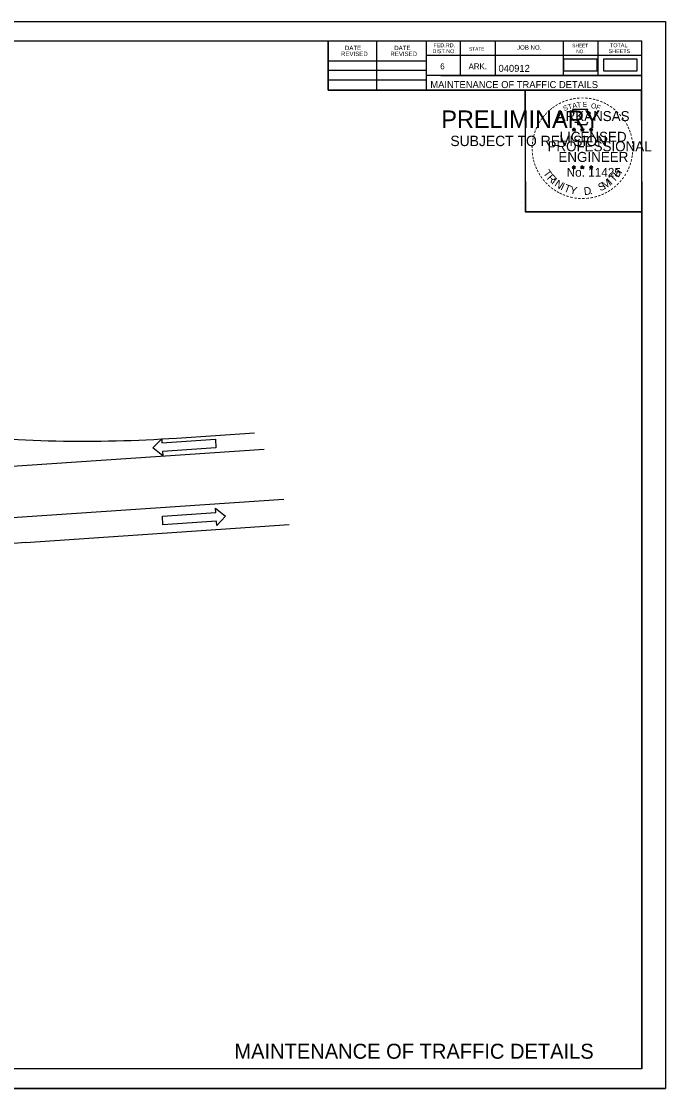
# Model space of a CAD drawing. Extents: x 13744624 to 13747958, y 3814079 to 3815145.
# Drawn here: x 13747314 to 13747958, y 3814079 to 3815145 of the extents above; entities that cross this region are included whole.
import ezdxf

# ---------------------------------------------------------------- set-up
doc = ezdxf.new("R2010")
doc.units = 0
for name, color, linetype in [('Default', 7, 'Continuous'), ('R_Border', 7, 'Continuous'), ('R_Border Notes', 7, 'Continuous'), ('R_Border PE', 7, 'Continuous'), ('R_Border Prem', 7, 'Continuous'), ('R_Exist Surface', 7, 'Continuous'), ('R_MOT', 7, 'Continuous'), ('R_No Plot', 7, 'Continuous')]:
    doc.layers.add(name, color=color, linetype=linetype)

msp = doc.modelspace()

# ---------------------------------------------------------------- linework, layer by layer
at = {"layer": 'Default'}
for points in [[(13747855.7, 3815096), (13747889.1, 3815096), (13747889.1, 3815107.6), (13747855.7, 3815107.6)], [(13747895.6, 3815096), (13747929, 3815096), (13747929, 3815107.6), (13747895.6, 3815107.6)]]:
    msp.add_lwpolyline(points, close=True, dxfattribs=at)
at = {"layer": 'R_Border'}
for p, q in [((13746352.9, 3815125.9), (13747933.8, 3815125.9)), ((13747620.6, 3815076.5), (13747620.6, 3815125.9)), ((13747669, 3815076.5), (13747669, 3815125.9)), ((13747718.3, 3815125.9), (13747718.3, 3815076.5)), ((13747752.5, 3815125.9), (13747752.5, 3815091.2)), ((13747787.2, 3815125.9), (13747787.2, 3815091.2)), ((13747855.1, 3815125.9), (13747855.1, 3815091.2)), ((13747889.8, 3815125.9), (13747889.8, 3815091.2)), ((13747933.8, 3814098.6), (13747933.8, 3815125.9)), ((13747620.6, 3815105.8), (13747718.3, 3815105.8)), ((13747933.8, 3815111.2), (13747718.3, 3815111.2)), ((13747933.8, 3815111.3), (13747933.8, 3815111.3)), ((13747620.6, 3815096.5), (13747718.3, 3815096.5)), ((13747620.6, 3815086.8), (13747718.3, 3815086.8)), ((13747933.8, 3815091.2), (13747718.3, 3815091.2)), ((13747733.1, 3815091.2), (13747933.8, 3815091.2)), ((13747933.8, 3815076.5), (13747620.6, 3815076.5)), ((13747933.8, 3814098.6), (13746352.9, 3814098.6))]:
    msp.add_line(p, q, dxfattribs=at)
at = {"layer": 'R_Border PE'}
for p, q in [((13747864.3, 3815037.8), (13747866, 3815037.2)), ((13747864.3, 3815037.8), (13747865.5, 3815037.6)), ((13747864.3, 3815037.8), (13747865.4, 3815037.2)), ((13747864.9, 3815035.8), (13747866, 3815037.2)), ((13747864.9, 3815035.8), (13747865.5, 3815037)), ((13747864.9, 3815035.8), (13747866, 3815036.8)), ((13747866, 3815039.1), (13747865.8, 3815037.8)), ((13747866, 3815037.2), (13747866, 3815039.1)), ((13747866, 3815039.1), (13747866.2, 3815037.8)), ((13747867.7, 3815037.8), (13747866, 3815037.2)), ((13747867.1, 3815035.8), (13747866, 3815037.2)), ((13747867.1, 3815035.8), (13747866, 3815036.8)), ((13747867.7, 3815037.8), (13747866.3, 3815037.6)), ((13747867.1, 3815035.8), (13747866.4, 3815037.2)), ((13747867.7, 3815037.8), (13747866.7, 3815037.3)), ((13747872.6, 3815037.8), (13747874.3, 3815037.2)), ((13747872.6, 3815037.8), (13747873.9, 3815037.6)), ((13747872.6, 3815037.8), (13747873.8, 3815037.2)), ((13747873.3, 3815035.8), (13747874.3, 3815037.2)), ((13747873.3, 3815035.8), (13747873.9, 3815037)), ((13747873.3, 3815035.8), (13747874.3, 3815036.8)), ((13747874.3, 3815039.1), (13747874.1, 3815037.8)), ((13747874.3, 3815037.2), (13747874.3, 3815039.1)), ((13747874.3, 3815039.1), (13747874.6, 3815037.8)), ((13747876.1, 3815037.8), (13747874.3, 3815037.2)), ((13747875.4, 3815035.8), (13747874.3, 3815037.2)), ((13747875.4, 3815035.8), (13747874.3, 3815036.8)), ((13747876.1, 3815037.8), (13747874.7, 3815037.6)), ((13747875.4, 3815035.8), (13747874.7, 3815037.2)), ((13747876.1, 3815037.8), (13747875.1, 3815037.3)), ((13747881.4, 3815037.7), (13747883.2, 3815037.2)), ((13747881.4, 3815037.7), (13747882.7, 3815037.5)), ((13747881.4, 3815037.7), (13747882.6, 3815037.1)), ((13747882.1, 3815035.7), (13747883.2, 3815037.2)), ((13747882.1, 3815035.7), (13747882.7, 3815036.9)), ((13747882.1, 3815035.7), (13747883.2, 3815036.8)), ((13747883.2, 3815039), (13747883, 3815037.7)), ((13747883.2, 3815037.2), (13747883.2, 3815039)), ((13747883.2, 3815039), (13747883.4, 3815037.8)), ((13747884.9, 3815037.7), (13747883.2, 3815037.2)), ((13747884.2, 3815035.7), (13747883.2, 3815037.2)), ((13747884.2, 3815035.7), (13747883.2, 3815036.8)), ((13747884.9, 3815037.7), (13747883.5, 3815037.5)), ((13747884.2, 3815035.7), (13747883.5, 3815037.2)), ((13747884.9, 3815037.7), (13747883.9, 3815037.2)), ((13747864.2, 3814999.9), (13747866, 3814999.4)), ((13747864.2, 3814999.9), (13747865.5, 3814999.7)), ((13747864.2, 3814999.9), (13747865.4, 3814999.3)), ((13747864.9, 3814997.9), (13747866, 3814999.4)), ((13747864.9, 3814997.9), (13747865.5, 3814999.1)), ((13747864.9, 3814997.9), (13747866, 3814999)), ((13747866, 3815001.2), (13747865.8, 3814999.9)), ((13747866, 3814999.4), (13747866, 3815001.2)), ((13747866, 3815001.2), (13747866.2, 3815000)), ((13747867.7, 3814999.9), (13747866, 3814999.4)), ((13747867, 3814997.9), (13747866, 3814999.4)), ((13747867.7, 3814999.9), (13747866.3, 3814999.7)), ((13747867, 3814997.9), (13747866.4, 3814999.3)), ((13747867.7, 3814999.9), (13747866.7, 3814999.4)), ((13747872.6, 3814999.9), (13747874.3, 3814999.4)), ((13747872.6, 3814999.9), (13747873.8, 3814999.7)), ((13747872.6, 3814999.9), (13747873.8, 3814999.3)), ((13747873.2, 3814997.9), (13747874.3, 3814999.4)), ((13747873.2, 3814997.9), (13747873.9, 3814999.1)), ((13747873.2, 3814997.9), (13747874.3, 3814999)), ((13747874.3, 3815001.2), (13747874.1, 3814999.9)), ((13747874.3, 3814999.4), (13747874.3, 3815001.2)), ((13747874.3, 3815001.2), (13747874.6, 3815000)), ((13747876.1, 3814999.9), (13747874.3, 3814999.4)), ((13747875.4, 3814997.9), (13747874.3, 3814999.4)), ((13747876.1, 3814999.9), (13747874.6, 3814999.7)), ((13747875.4, 3814997.9), (13747874.7, 3814999.3)), ((13747876.1, 3814999.9), (13747875, 3814999.4)), ((13747881.4, 3814999.9), (13747883.2, 3814999.3)), ((13747881.4, 3814999.9), (13747882.7, 3814999.7)), ((13747881.4, 3814999.9), (13747882.6, 3814999.3)), ((13747882.1, 3814997.8), (13747883.2, 3814999.3)), ((13747882.1, 3814997.8), (13747882.7, 3814999.1)), ((13747883.2, 3815001.2), (13747883, 3814999.9)), ((13747883.2, 3814999.3), (13747883.2, 3815001.2)), ((13747883.2, 3815001.2), (13747883.4, 3814999.9)), ((13747884.9, 3814999.9), (13747883.2, 3814999.3)), ((13747884.2, 3814997.8), (13747883.2, 3814999.3)), ((13747884.9, 3814999.9), (13747883.5, 3814999.6)), ((13747884.2, 3814997.8), (13747883.5, 3814999.3)), ((13747884.9, 3814999.9), (13747883.9, 3814999.4)), ((13747867, 3814997.9), (13747866, 3814999)), ((13747875.4, 3814997.9), (13747874.3, 3814999)), ((13747882.1, 3814997.8), (13747883.1, 3814998.9)), ((13747884.2, 3814997.8), (13747883.1, 3814998.9))]:
    msp.add_line(p, q, dxfattribs=at)
for points in [[(13747864.5, 3815057.2), (13747865.8, 3815053.1)], [(13747882, 3815052.6), (13747882.7, 3815054), (13747879.3, 3815053.9), (13747880, 3815057.2), (13747864.5, 3815057.2)], [(13747866.9, 3815045.1), (13747866.9, 3815044.6), (13747869.7, 3815044.5), (13747869.5, 3815042.2), (13747878.8, 3815042.2), (13747879.8, 3815044.9)], [(13747866, 3815039.1), (13747867.1, 3815035.8), (13747864.3, 3815037.8), (13747867.7, 3815037.8), (13747864.9, 3815035.8), (13747866, 3815039.1)], [(13747874.3, 3815039.1), (13747875.4, 3815035.8), (13747872.6, 3815037.8), (13747876.1, 3815037.8), (13747873.3, 3815035.8), (13747874.3, 3815039.1)], [(13747883.2, 3815039), (13747884.2, 3815035.7), (13747881.4, 3815037.7), (13747884.9, 3815037.7), (13747882.1, 3815035.7), (13747883.2, 3815039)], [(13747866, 3815001.2), (13747867, 3814997.9), (13747864.2, 3814999.9), (13747867.7, 3814999.9), (13747864.9, 3814997.9), (13747866, 3815001.2)], [(13747874.3, 3815001.2), (13747875.4, 3814997.9), (13747872.6, 3814999.9), (13747876.1, 3814999.9), (13747873.2, 3814997.9), (13747874.3, 3815001.2)], [(13747883.2, 3815001.2), (13747884.2, 3814997.8), (13747881.4, 3814999.9), (13747884.9, 3814999.9), (13747882.1, 3814997.8), (13747883.2, 3815001.2)]]:
    msp.add_lwpolyline(points, dxfattribs=at)
for centre, radius in [((13747866, 3815037.2), 0.861), ((13747866, 3815037.2), 0.723), ((13747866, 3815037.2), 0.579), ((13747866, 3815037.2), 0.495), ((13747866, 3815037.2), 0.374), ((13747866, 3815037.2), 0.248), ((13747866, 3815037.2), 0.148), ((13747874.3, 3815037.2), 0.861), ((13747874.3, 3815037.2), 0.723), ((13747874.3, 3815037.2), 0.579), ((13747874.3, 3815037.2), 0.495), ((13747874.3, 3815037.2), 0.374), ((13747874.3, 3815037.2), 0.248), ((13747874.3, 3815037.2), 0.148), ((13747883.2, 3815037.2), 0.861), ((13747883.2, 3815037.2), 0.723), ((13747883.2, 3815037.2), 0.579), ((13747883.2, 3815037.2), 0.495), ((13747883.2, 3815037.2), 0.374), ((13747883.2, 3815037.2), 0.248), ((13747883.2, 3815037.2), 0.148), ((13747866, 3814999.4), 0.861), ((13747866, 3814999.4), 0.723), ((13747866, 3814999.4), 0.579), ((13747866, 3814999.4), 0.495), ((13747866, 3814999.4), 0.374), ((13747866, 3814999.4), 0.248), ((13747866, 3814999.4), 0.148), ((13747874.3, 3814999.4), 0.861), ((13747874.3, 3814999.4), 0.723), ((13747874.3, 3814999.4), 0.579), ((13747874.3, 3814999.4), 0.495), ((13747874.3, 3814999.4), 0.374), ((13747874.3, 3814999.4), 0.248), ((13747874.3, 3814999.4), 0.148), ((13747883.2, 3814999.3), 0.861), ((13747883.2, 3814999.3), 0.723), ((13747883.2, 3814999.3), 0.579), ((13747883.2, 3814999.3), 0.495), ((13747883.2, 3814999.3), 0.374), ((13747883.2, 3814999.3), 0.248), ((13747883.2, 3814999.3), 0.148)]:
    msp.add_circle(centre, radius, dxfattribs=at)
at = {"layer": 'R_Exist Surface'}
for p, q in [((13747469, 3814728.9), (13747547.1, 3814734.3)), ((13746618.3, 3814653.8), (13747556.5, 3814717.9)), ((13746622.2, 3814602.8), (13747576.4, 3814667.9)), ((13747318.4, 3814624.5), (13747581.5, 3814642.4))]:
    msp.add_line(p, q, dxfattribs=at)
for centre, start, end in [((13747376.6, 3816084.6), 263.7335, 273.9), ((13747410.9, 3813268.8), 93.9033, 109.9033)]:
    msp.add_arc(centre, 1358.8, start, end, dxfattribs=at)
at = {"layer": 'R_MOT'}
for p, q in [((13747445.5, 3814719.1), (13747454.3, 3814728.3)), ((13747454.3, 3814728.3), (13747454.6, 3814724.1)), ((13747454.6, 3814724.1), (13747508, 3814727.7)), ((13747508, 3814727.7), (13747508.5, 3814719.2)), ((13747455.4, 3814711.2), (13747445.5, 3814719.1)), ((13747508.5, 3814719.2), (13747455.1, 3814715.5)), ((13747455.1, 3814715.5), (13747455.4, 3814711.2)), ((13747508.5, 3814654.4), (13747508.2, 3814658.7)), ((13747508.2, 3814658.7), (13747518.1, 3814650.8)), ((13747455, 3814650.8), (13747508.5, 3814654.4)), ((13747455.6, 3814642.2), (13747455, 3814650.8)), ((13747518.1, 3814650.8), (13747509.3, 3814641.6)), ((13747509, 3814645.9), (13747455.6, 3814642.2)), ((13747509.3, 3814641.6), (13747509, 3814645.9))]:
    msp.add_line(p, q, dxfattribs=at)
at = {"layer": 'R_No Plot'}
for p, q in [((13746290.9, 3815145.4), (13747957.6, 3815145.4)), ((13747814, 3814964.2), (13747814, 3814964.2)), ((13746290.9, 3814078.7), (13747957.6, 3814078.7))]:
    msp.add_line(p, q, dxfattribs=at)
for points in [[(13746290.9, 3815145.4), (13747957.6, 3815145.4), (13747957.6, 3814078.7), (13746290.9, 3814078.7)], [(13747522.5, 3815125.9), (13747620.6, 3815125.9), (13747620.6, 3815076.5), (13747701.2, 3815076.5), (13747817.2, 3815076.5), (13747817.2, 3814954.9), (13747933.8, 3814954.9), (13747933.8, 3814098.6), (13746352.9, 3814098.6), (13746352.9, 3815125.9)], [(13747817.2, 3815076.5), (13747933.2, 3815076.5), (13747933.8, 3814954.9), (13747817.8, 3814954.9)]]:
    msp.add_lwpolyline(points, close=True, dxfattribs=at)

# ---------------------------------------------------------------- texts
at = {"layer": 'R_Border'}
for s, height, p in [('DATE', 4.4, (13747637.3, 3815116.6)), ('DATE', 4.4, (13747686.6, 3815116.6)), ('DIST.NO.', 3.91, (13747724.7, 3815113.6)), ('FED.RD.', 3.91, (13747725.7, 3815119.5)), ('STATE', 3.42, (13747761.3, 3815116.1)), ('JOB NO.', 4.4, (13747809.2, 3815117.1)), ('SHEET', 3.42, (13747864.4, 3815119.5)), ('NO.', 3.42, (13747868.3, 3815113.6)), ('SHEETS', 3.91, (13747900.6, 3815113.6)), ('TOTAL', 3.91, (13747902, 3815119.5)), ('REVISED', 4.4, (13747633.4, 3815110.7)), ('REVISED', 4.4, (13747682.7, 3815110.7)), ('6', 5.86, (13747732.5, 3815097.5)), ('ARK.', 5.86, (13747760.8, 3815097.5)), ('040912', 7, (13747790.7, 3815094.9)), ('MAINTENANCE OF TRAFFIC DETAILS', 7, (13747722.6, 3815078.7))]:
    msp.add_text(s, height=height, dxfattribs=at).set_placement(p)
at = {"layer": 'R_Border Notes'}
msp.add_text('MAINTENANCE OF TRAFFIC DETAILS', height=15, dxfattribs=at).set_placement((13747526.9, 3814108.6))
at = {"layer": 'R_Border PE'}
for s, height, rotation, p in [('-', 8, 28.7918, (13747851.9, 3815059.9)), ('-', 8, 24.3072, (13747855, 3815061.5)), ('-', 8, 19.1761, (13747858.2, 3815062.8)), ('T', 5, 16.4036, (13747860.8, 3815057.2)), ('-', 8, 13.6302, (13747861.9, 3815064)), ('A', 5, 11.2132, (13747864.9, 3815058.5)), ('-', 8, 10.2193, (13747865.3, 3815064.8)), ('T', 5, 6.0228, (13747869.2, 3815059.3)), ('-', 8, 5.8968, (13747869, 3815065.4)), ('-', 8, 0.1862, (13747872.8, 3815065.7)), ('E', 5, 0.8323, (13747874.7, 3815059.9)), ('-', 8, 357.743, (13747876.5, 3815065.7)), ('-', 8, 352.1617, (13747880.2, 3815065.4)), ('O', 5, 350.4515, (13747882.7, 3815058.8)), ('-', 8, 347.2049, (13747883.8, 3815064.8)), ('-', 8, 342.3362, (13747886.9, 3815064.1)), ('-', 8, 337.8551, (13747890.6, 3815062.9)), ('-', 8, 334.1211, (13747893.8, 3815061.6)), ('-', 8, 329.6409, (13747896.7, 3815060.2)), ('-', 8, 48.4231, (13747839.2, 3815049.7)), ('-', 8, 42.9622, (13747841.4, 3815052.1)), ('-', 8, 38.9507, (13747843.6, 3815054.2)), ('-', 8, 36.2317, (13747846, 3815056.1)), ('-', 8, 34.0636, (13747848.9, 3815058)), ('S', 5, 21.594, (13747856.2, 3815055.6)), ('F', 5, 340.0707, (13747887.5, 3815057.7)), ('-', 8, 325.8627, (13747899.9, 3815058.4)), ('-', 8, 320.5297, (13747902.9, 3815056.2)), ('-', 8, 315.5786, (13747905.9, 3815053.8)), ('-', 8, 309.8797, (13747908.8, 3815051)), ('-', 8, 62.8713, (13747831.9, 3815038.7)), ('-', 8, 58.0706, (13747833.5, 3815041.8)), ('-', 8, 54.2325, (13747835.1, 3815044.4)), ('-', 8, 50.6142, (13747837.2, 3815047.3)), ('-', 8, 306.6522, (13747911.4, 3815048)), ('-', 7, 303.6753, (13747913.8, 3815045.2)), ('-', 8, 299.6684, (13747915.4, 3815042.2)), ('-', 8, 75.461, (13747828.6, 3815029)), ('-', 8, 72.3945, (13747829.5, 3815032.5)), ('-', 8, 67.7743, (13747830.6, 3815035.7)), ('-', 8, 294.6628, (13747917, 3815039.1)), ('-', 8, 290.5728, (13747918.3, 3815036.2)), ('-', 8, 285.1233, (13747919.5, 3815033.3)), ('-', 8, 89.0622, (13747827.4, 3815018.4)), ('-', 8, 85.1863, (13747827.5, 3815021.9)), ('-', 8, 81.2013, (13747827.9, 3815025.4)), ('-', 8, 280.5493, (13747920.5, 3815029.6)), ('-', 8, 276.5962, (13747921.3, 3815025.8)), ('-', 8, 274.3301, (13747921.6, 3815022.2)), ('-', 8, 94.1959, (13747827.6, 3815014.8)), ('-', 8, 98.9479, (13747827.9, 3815011.5)), ('-', 8, 101.7149, (13747828.6, 3815007.8)), ('-', 8, 260.9953, (13747921.3, 3815012.4)), ('-', 8, 263.5172, (13747921.7, 3815015.7)), ('-', 8, 269.9407, (13747921.8, 3815019)), ('-', 8, 105.4578, (13747829.4, 3815004.8)), ('-', 8, 109.0874, (13747830.5, 3815001.7)), ('-', 8, 114.0643, (13747831.8, 3814998.7)), ('-', 8, 247.8887, (13747918.8, 3815002)), ('-', 8, 252.8681, (13747919.9, 3815005.4)), ('-', 8, 255.7626, (13747920.8, 3815009)), ('-', 8, 115.7289, (13747833.3, 3814995.6)), ('-', 8, 120.4471, (13747835.1, 3814992.7)), ('-', 8, 125.8934, (13747837.1, 3814989.9)), ('T', 7.7, 306.0406, (13747834.8, 3814993.6)), ('R', 7.7, 314.005, (13747838.6, 3814988.3)), ('I', 7.7, 321.9694, (13747843.1, 3814983.7)), ('I', 7.7, 42.1136, (13747903.1, 3814981.6)), ('T', 7.7, 46.6444, (13747905.9, 3814984)), ('H', 7.7, 54.6088, (13747910.4, 3814988.7)), ('-', 8, 233.8452, (13747913.5, 3814991.9)), ('-', 8, 239.0712, (13747915.5, 3814995.1)), ('-', 8, 244.6197, (13747917.5, 3814998.9)), ('-', 8, 130.7181, (13747839.4, 3814987.1)), ('-', 8, 134.2238, (13747842, 3814984.4)), ('-', 8, 138.9338, (13747844.6, 3814982.1)), ('-', 8, 144.6463, (13747847.4, 3814980)), ('N', 7.7, 326.5002, (13747845.9, 3814981.3)), ('I', 7.7, 335.3603, (13747852, 3814977.4)), ('T', 7.7, 339.8912, (13747855.3, 3814975.7)), ('Y', 7.7, 347.8556, (13747861.4, 3814973.5)), ('D', 7.7, 6.3969, (13747876.3, 3814971.7)), ('S', 7.7, 26.9312, (13747892.5, 3814975.4)), ('M', 7.7, 32.6563, (13747896.7, 3814977.4)), ('-', 8, 215.7363, (13747903.6, 3814981.3)), ('-', 8, 221.0851, (13747906.3, 3814983.7)), ('-', 8, 225.7653, (13747908.9, 3814986.2)), ('-', 8, 231.2538, (13747911.3, 3814989)), ('-', 8, 148.0898, (13747850.2, 3814978.2)), ('-', 8, 151.5704, (13747853.1, 3814976.6)), ('-', 8, 154.6002, (13747855.7, 3814975.3)), ('-', 8, 158.5612, (13747858.8, 3814974.1)), ('-', 8, 162.7983, (13747862.2, 3814973)), ('-', 8, 167.5555, (13747865.8, 3814972.2)), ('-', 8, 173.1155, (13747869.7, 3814971.6)), ('-', 8, 176.5183, (13747873.4, 3814971.4)), ('-', 8, 181.5918, (13747877.1, 3814971.4)), ('-', 8, 185.8167, (13747881.2, 3814971.8)), ('-', 8, 191.2858, (13747884.9, 3814972.5)), ('.', 7.7, 13.7642, (13747882.2, 3814972.4)), ('-', 8, 195.4743, (13747888.5, 3814973.5)), ('-', 8, 200.7184, (13747891.9, 3814974.7)), ('-', 8, 204.2516, (13747895, 3814976.1)), ('-', 8, 207.3568, (13747898.1, 3814977.7)), ('-', 8, 212.2491, (13747900.9, 3814979.4))]:
    msp.add_text(s, height=height, rotation=rotation, dxfattribs=at).set_placement(p)
for s, height, p in [('ARKANSAS', 10, (13747848.7, 3815045.7)), ('LICENSED', 10, (13747851.7, 3815025)), ('DWB', 0.05, (13747865.9, 3815037.2)), ('DWB', 0.05, (13747874.3, 3815037.2)), ('DWB', 0.05, (13747883.1, 3815037.2)), ('PROFESSIONAL', 10, (13747839.6, 3815015.5)), ('ENGINEER', 10, (13747850.5, 3815004.9)), ('No. 11425', 8.78, (13747858.7, 3814990.1)), ('DWB', 0.05, (13747865.9, 3814999.4)), ('DWB', 0.05, (13747874.3, 3814999.4)), ('DWB', 0.05, (13747883.1, 3814999.3))]:
    msp.add_text(s, height=height, dxfattribs=at).set_placement(p)
at = {"layer": 'R_Border Prem'}
for s, height, p in [('PRELIMINARY', 17.5, (13747733.6, 3815038.8)), ('DWB', 0.05, (13747737.3, 3815048.1)), ('SUBJECT TO REVISION', 10.376, (13747742.6, 3815020.7))]:
    msp.add_text(s, height=height, dxfattribs=at).set_placement(p)

doc.saveas('drawing.dxf')
